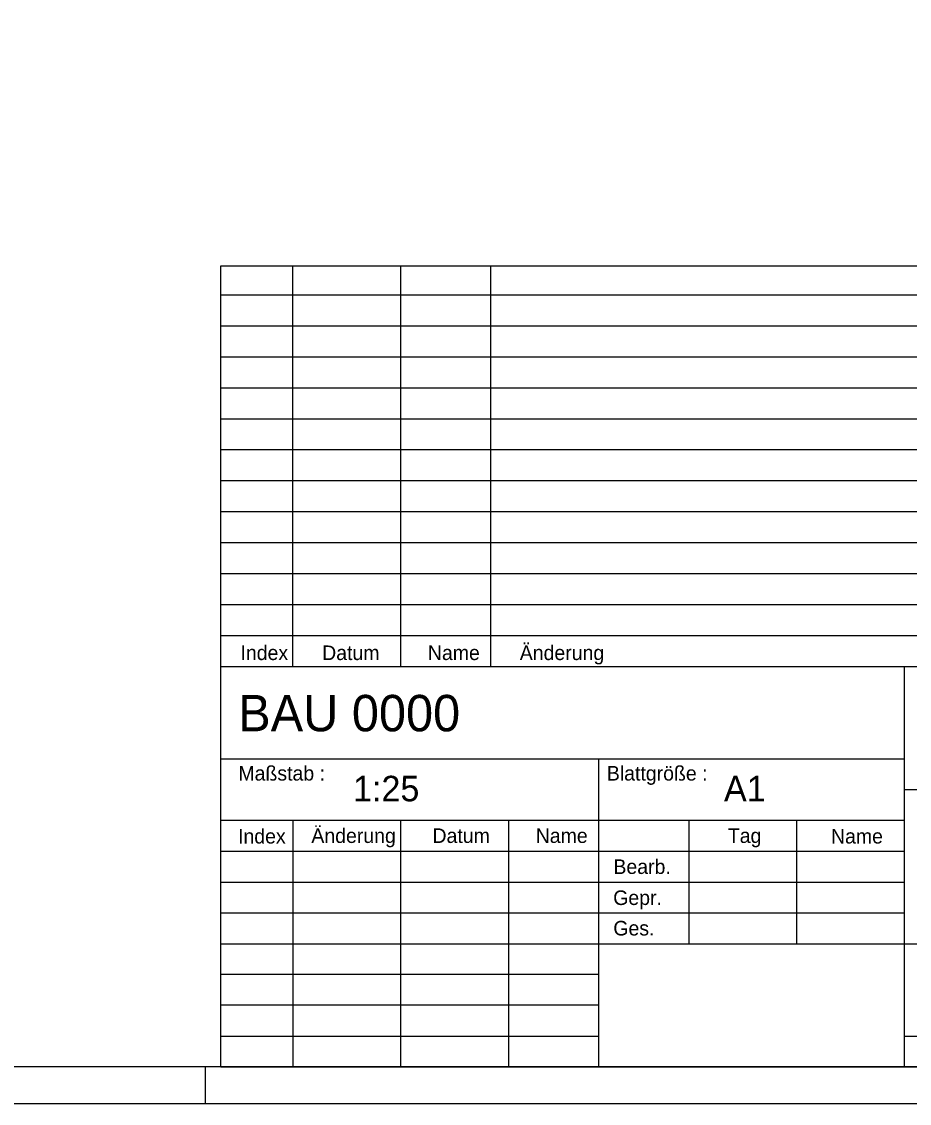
# Model space of a CAD drawing. Extents: x 0 to 21, y 0 to 14.9.
# Drawn here: x 15.769 to 18.816, y 0 to 3.713 of the extents above; entities that cross this region are included whole.
import ezdxf

# ---------------------------------------------------------------- set-up
doc = ezdxf.new("R2010")
doc.units = 0
doc.layers.add('90_Plankopf', color=7, linetype='Continuous')

msp = doc.modelspace()

# ---------------------------------------------------------------- linework, layer by layer
at = {"layer": '90_Plankopf'}
for p, q in [((16.453, 1.4998), (16.453, 2.8745)), ((16.453, 2.8745), (20.9, 2.8745)), ((16.7001, 1.4998), (16.7001, 2.8745)), ((17.0707, 1.4998), (17.0707, 2.8745)), ((17.3795, 1.4998), (17.3795, 2.8745)), ((16.453, 2.7748), (20.9, 2.7748)), ((16.453, 2.6685), (20.9, 2.6685)), ((16.453, 2.5623), (20.9, 2.5623)), ((16.453, 2.456), (20.9, 2.456)), ((16.453, 2.3498), (20.9, 2.3498)), ((16.453, 2.2435), (20.9, 2.2435)), ((16.453, 2.1373), (20.9, 2.1373)), ((16.453, 2.031), (20.9, 2.031)), ((16.453, 1.9248), (20.9, 1.9248)), ((16.453, 1.8185), (20.9, 1.8185)), ((16.453, 1.7123), (20.9, 1.7123)), ((16.453, 1.606), (20.9, 1.606)), ((16.453, 1.4998), (20.9, 1.4998)), ((16.453, 0.125), (16.453, 1.4998)), ((16.453, 1.4998), (20.9, 1.4998)), ((18.8, 0.125), (18.8, 1.4998)), ((16.453, 1.1825), (18.8, 1.1825)), ((17.7501, 0.125), (17.7501, 1.1825)), ((18.8, 1.0768), (20.9, 1.0768)), ((16.453, 0.9718), (18.8, 0.9718)), ((16.7001, 0.971), (16.7001, 0.125)), ((17.0707, 0.125), (17.0707, 0.971)), ((17.4412, 0.125), (17.4412, 0.971)), ((18.0589, 0.971), (18.0589, 0.548)), ((18.4295, 0.548), (18.4295, 0.971)), ((16.453, 0.8658), (18.8, 0.8658)), ((16.453, 0.7595), (18.8, 0.7595)), ((16.453, 0.6538), (18.8, 0.6538)), ((16.453, 0.548), (18.8, 0.548)), ((16.453, 0.548), (18.8, 0.548)), ((17.7501, 0.548), (18.8, 0.548)), ((18.8, 0.548), (20.9, 0.548)), ((17.7501, 0.4423), (16.453, 0.4423)), ((17.7501, 0.3365), (16.453, 0.3365)), ((16.453, 0.2308), (17.7501, 0.2308)), ((18.8, 0.2308), (20.9, 0.2308)), ((16.4, 0), (16.4, 0.125)), ((20.9, 0.125), (16.453, 0.125)), ((16.453, 0.125), (17.7501, 0.125)), ((16.745, 0.125), (20.9, 0.125)), ((16.745, 0.125), (20.9, 0.125))]:
    msp.add_line(p, q, dxfattribs=at)
for points in [[(0, 0), (21.025, 0), (21.025, 14.85), (0, 14.85)], [(0.625, 14.725), (20.9, 14.725), (20.9, 0.125), (0.625, 0.125)]]:
    msp.add_lwpolyline(points, close=True, dxfattribs=at)

# ---------------------------------------------------------------- texts
for s, height, p in [('Index', 0.05, (16.5201, 1.5214)), ('Datum', 0.05, (16.8004, 1.5214)), ('Name', 0.05, (17.1635, 1.5214)), ('Änderung', 0.05, (17.4789, 1.5214)), ('BAU 0000      ', 0.125, (16.5123, 1.2769)), ('Maßstab :', 0.05, (16.5129, 1.1079)), ('Blattgröße :', 0.049998, (17.7779, 1.1079)), ('1:25     ', 0.0875, (16.9065, 1.0367)), ('A1       ', 0.0875, (18.18, 1.0367)), ('Index', 0.05, (16.5117, 0.8918)), ('Änderung', 0.05, (16.7634, 0.8937)), ('Datum', 0.05, (17.1792, 0.8937)), ('Name', 0.05, (17.5337, 0.8937)), ('Tag', 0.05, (18.1931, 0.8937)), ('Name', 0.05, (18.5473, 0.8918)), ('Bearb.', 0.05, (17.8004, 0.7873)), ('Gepr.', 0.05, (17.7997, 0.6808)), ('Ges.', 0.05, (17.8001, 0.5762))]:
    msp.add_text(s, height=height, dxfattribs=at).set_placement(p)

doc.saveas('drawing.dxf')
